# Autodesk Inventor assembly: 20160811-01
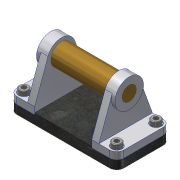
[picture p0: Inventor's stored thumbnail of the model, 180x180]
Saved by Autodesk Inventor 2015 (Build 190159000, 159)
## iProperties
Created: 2016-08
Part Number: 20160811-01
Document SubType Name: Assembly
Designer: navara
Author: navara
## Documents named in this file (4)
- D:\20160811\20160811-01.iam
- D:\20160811\20160811-01.ipt
- D:\Dokumenty\CAD_DATA\Inventor_2015\Content Center Files\R2015\cs-CZ\ISO 4762(2)\ISO 4762 - M8 x 16ISO.ipt
- D:\20160811\20160811-02.iam
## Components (6 placed, 3 different names)
1. 20160811-02:3 [sub-assembly]
2. 20160811-01:1
3. ISO 4762 M8 x 16:1
4. ISO 4762 M8 x 16:2
5. ISO 4762 M8 x 16:3
6. ISO 4762 M8 x 16:4
